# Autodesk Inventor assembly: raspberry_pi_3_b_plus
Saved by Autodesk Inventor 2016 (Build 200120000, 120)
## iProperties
Created: 2018-05
Part Number: raspberry_pi_3_b_plus
Document SubType Name: Assembly
Designer: Administrator
Title: raspberry_pi_3_b_plus v38
Author: Administrator
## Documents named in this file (33)
- c:\worker\convert-fusion-mar-2018\tmp\job-1\16\output\files\8c58ff39-88bb-4352-afd9-60265520bae5\05ab2b07-ca50-4e2e-bbe0-02242daedd4e.iam
- c:\worker\convert-fusion-mar-2018\tmp\job-1\16\output\files\8c58ff39-88bb-4352-afd9-60265520bae5\pcb.ipt
- c:\worker\convert-fusion-mar-2018\tmp\job-1\16\output\files\8c58ff39-88bb-4352-afd9-60265520bae5\micro_usb_connector v17.iam
- c:\worker\convert-fusion-mar-2018\tmp\job-1\16\output\files\8c58ff39-88bb-4352-afd9-60265520bae5\sd_card_slot_molex v11.iam
- c:\worker\convert-fusion-mar-2018\tmp\job-1\16\output\files\8c58ff39-88bb-4352-afd9-60265520bae5\Pin Header 20x2 TH Pitch 2.54mm v1.iam
- c:\worker\convert-fusion-mar-2018\tmp\job-1\16\output\files\8c58ff39-88bb-4352-afd9-60265520bae5\USB-A-stack-1x2 v23.iam
- c:\worker\convert-fusion-mar-2018\tmp\job-1\16\output\files\8c58ff39-88bb-4352-afd9-60265520bae5\USB-A-stack-1x2 v23_1.iam
- c:\worker\convert-fusion-mar-2018\tmp\job-1\16\output\files\8c58ff39-88bb-4352-afd9-60265520bae5\te_1-1734248-5.ipt
- c:\worker\convert-fusion-mar-2018\tmp\job-1\16\output\files\8c58ff39-88bb-4352-afd9-60265520bae5\Pin Header 2x2 TH Pitch 2.54mm v1.iam
- c:\worker\convert-fusion-mar-2018\tmp\job-1\16\output\files\8c58ff39-88bb-4352-afd9-60265520bae5\SOP-3_1.6mm.ipt
- c:\worker\convert-fusion-mar-2018\tmp\job-1\16\output\files\8c58ff39-88bb-4352-afd9-60265520bae5\EDAC_1743_RJ45_TH v18.iam
- c:\worker\convert-fusion-mar-2018\tmp\job-1\16\output\files\8c58ff39-88bb-4352-afd9-60265520bae5\qfn32_5mm v3.ipt
- c:\worker\convert-fusion-mar-2018\tmp\job-1\16\output\files\8c58ff39-88bb-4352-afd9-60265520bae5\qfn48_9mm v3.ipt
- c:\worker\convert-fusion-mar-2018\tmp\job-1\16\output\files\8c58ff39-88bb-4352-afd9-60265520bae5\TSOP-6 2mm v1.ipt
- c:\worker\convert-fusion-mar-2018\tmp\job-1\16\output\files\8c58ff39-88bb-4352-afd9-60265520bae5\TSOP-6 3mm v3.ipt
- c:\worker\convert-fusion-mar-2018\tmp\job-1\16\output\files\8c58ff39-88bb-4352-afd9-60265520bae5\qfp16_3x2mm v5.iam
- c:\worker\convert-fusion-mar-2018\tmp\job-1\16\output\files\8c58ff39-88bb-4352-afd9-60265520bae5\wifi.iam
- c:\worker\convert-fusion-mar-2018\tmp\job-1\16\output\files\8c58ff39-88bb-4352-afd9-60265520bae5\qfn80_12mm v3.ipt
- c:\worker\convert-fusion-mar-2018\tmp\job-1\16\output\files\8c58ff39-88bb-4352-afd9-60265520bae5\crystal_dfn4 v1.iam
- c:\worker\convert-fusion-mar-2018\tmp\job-1\16\output\files\8c58ff39-88bb-4352-afd9-60265520bae5\bcm2837 v8.ipt
- c:\worker\convert-fusion-mar-2018\tmp\job-1\16\output\files\8c58ff39-88bb-4352-afd9-60265520bae5\wlbga140_5mm v2.ipt
- c:\worker\convert-fusion-mar-2018\tmp\job-1\16\output\files\8c58ff39-88bb-4352-afd9-60265520bae5\cap0603_03 v2.ipt
- c:\worker\convert-fusion-mar-2018\tmp\job-1\16\output\files\8c58ff39-88bb-4352-afd9-60265520bae5\cap0402 v1.ipt
- c:\worker\convert-fusion-mar-2018\tmp\job-1\16\output\files\8c58ff39-88bb-4352-afd9-60265520bae5\resistor_0402 v1.ipt
- c:\worker\convert-fusion-mar-2018\tmp\job-1\16\output\files\8c58ff39-88bb-4352-afd9-60265520bae5\cap1206 v4.ipt
- c:\worker\convert-fusion-mar-2018\tmp\job-1\16\output\files\8c58ff39-88bb-4352-afd9-60265520bae5\ind2520 v1.ipt
- c:\worker\convert-fusion-mar-2018\tmp\job-1\16\output\files\8c58ff39-88bb-4352-afd9-60265520bae5\ledra_0603 v2.ipt
- c:\worker\convert-fusion-mar-2018\tmp\job-1\16\output\files\8c58ff39-88bb-4352-afd9-60265520bae5\pj-322 v8.iam
- c:\worker\convert-fusion-mar-2018\tmp\job-1\16\output\files\8c58ff39-88bb-4352-afd9-60265520bae5\SOP-3 v1.ipt
- c:\worker\convert-fusion-mar-2018\tmp\job-1\16\output\files\8c58ff39-88bb-4352-afd9-60265520bae5\SOP-3 2.5mm v3.ipt
- c:\worker\convert-fusion-mar-2018\tmp\job-1\16\output\files\8c58ff39-88bb-4352-afd9-60265520bae5\capar2_1013 v1.ipt
- c:\worker\convert-fusion-mar-2018\tmp\job-1\16\output\files\8c58ff39-88bb-4352-afd9-60265520bae5\molex hdmi smt v8.iam
- c:\worker\convert-fusion-mar-2018\tmp\job-1\16\output\files\8c58ff39-88bb-4352-afd9-60265520bae5\TSOP-2 4mm v2.ipt
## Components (213 placed, 32 different names)
1. pcb:1
2. micro_usb_connector v17:1 [sub-assembly]
3. sd_card_slot_molex v11:1 [sub-assembly]
4. Pin Header 20x2 TH Pitch 2.54mm v1:1 [sub-assembly]
5. USB-A-stack-1x2 v23:1 [sub-assembly]
6. USB-A-stack-1x2 v23:2 [sub-assembly]
7. te_1-1734248-5:1
8. Pin Header 2x2 TH Pitch 2.54mm v1:1 [sub-assembly]
9. te_1-1734248-5:2
10. SOP-3_1.6mm:1
11. EDAC_1743_RJ45_TH v18:1 [sub-assembly]
12. SOP-3_1.6mm:1:1
13. SOP-3_1.6mm:2
14. SOP-3_1.6mm:3
15. qfn32_5mm v3:1
16. qfn48_9mm v3:1
17. TSOP-6 2mm v1:1
18. TSOP-6 3mm v3:1
19. qfp16_3x2mm v5:1 [sub-assembly]
20. wifi:1 [sub-assembly]
21. qfn80_12mm v3:1
22. crystal_dfn4 v1:1 [sub-assembly]
23. bcm2837 v8:1
24. wlbga140_5mm v2:1
25. cap0603_03 v2:1
26. cap0603_03 v2:2
27. cap0603_03 v2:3
28. cap0603_03 v2:4
29. cap0603_03 v2:5
30. cap0603_03 v2:6
31. cap0603_03 v2:7
32. cap0603_03 v2:8
33. cap0402 v1:1
34. cap0402 v1:2
35. cap0402 v1:3
36. cap0402 v1:4
37. cap0402 v1:5
38. cap0402 v1:6
39. cap0402 v1:7
40. cap0402 v1:8
41. cap0402 v1:9
42. cap0402 v1:10
43. cap0402 v1:11
44. cap0402 v1:12
45. cap0402 v1:13
46. cap0402 v1:14
47. cap0402 v1:15
48. cap0402 v1:16
49. cap0402 v1:17
50. cap0402 v1:18
51. cap0402 v1:19
52. cap0402 v1:20
53. cap0402 v1:21
54. cap0402 v1:22
55. cap0402 v1:23
56. cap0402 v1:24
57. cap0402 v1:25
58. cap0402 v1:26
59. cap0402 v1:27
60. cap0402 v1:28
61. cap0402 v1:29
62. cap0402 v1:30
63. cap0402 v1:31
64. cap0402 v1:32
65. cap0402 v1:33
66. cap0402 v1:34
67. cap0402 v1:35
68. cap0402 v1:36
69. cap0402 v1:37
70. resistor_0402 v1:1
71. resistor_0402 v1:2
72. resistor_0402 v1:3
73. resistor_0402 v1:4
74. resistor_0402 v1:5
75. cap0402 v1:38
76. cap0402 v1:39
77. resistor_0402 v1:6
78. cap0402 v1:40
79. cap0402 v1:41
80. resistor_0402 v1:7
81. resistor_0402 v1:8
82. resistor_0402 v1:9
83. resistor_0402 v1:10
84. resistor_0402 v1:11
85. resistor_0402 v1:12
86. resistor_0402 v1:13
87. resistor_0402 v1:14
88. resistor_0402 v1:15
89. resistor_0402 v1:16
90. resistor_0402 v1:17
91. resistor_0402 v1:18
92. resistor_0402 v1:19
93. resistor_0402 v1:20
94. resistor_0402 v1:21
95. resistor_0402 v1:22
96. resistor_0402 v1:23
97. resistor_0402 v1:24
98. resistor_0402 v1:25
99. resistor_0402 v1:26
100. resistor_0402 v1:27
101. resistor_0402 v1:28
102. resistor_0402 v1:29
103. resistor_0402 v1:30
104. resistor_0402 v1:31
105. resistor_0402 v1:32
106. resistor_0402 v1:33
107. resistor_0402 v1:34
108. resistor_0402 v1:35
109. resistor_0402 v1:36
110. resistor_0402 v1:37
111. resistor_0402 v1:38
112. cap0402 v1:42
113. resistor_0402 v1:39
114. resistor_0402 v1:40
115. cap1206 v4:1
116. cap1206 v4:2
117. cap1206 v4:3
118. cap1206 v4:4
119. cap1206 v4:5
120. cap1206 v4:6
121. cap1206 v4:7
122. cap1206 v4:8
123. cap1206 v4:9
124. cap1206 v4:10
125. cap1206 v4:11
126. cap0603_03 v2:9
127. cap0603_03 v2:10
128. cap0603_03 v2:11
129. cap0603_03 v2:12
130. cap0603_03 v2:13
131. cap0603_03 v2:14
132. cap0603_03 v2:15
133. crystal_dfn4 v1:2 [sub-assembly]
134. resistor_0402 v1:41
135. resistor_0402 v1:42
136. resistor_0402 v1:43
137. resistor_0402 v1:44
138. resistor_0402 v1:45
139. resistor_0402 v1:46
140. resistor_0402 v1:47
141. resistor_0402 v1:48
142. resistor_0402 v1:49
143. resistor_0402 v1:50
144. resistor_0402 v1:51
145. resistor_0402 v1:52
146. resistor_0402 v1:53
147. resistor_0402 v1:54
148. resistor_0402 v1:55
149. resistor_0402 v1:56
150. resistor_0402 v1:57
151. cap0402 v1:43
152. cap0402 v1:44
153. cap0402 v1:45
154. cap0402 v1:46
155. ind2520 v1:1
156. ind2520 v1:2
157. ind2520 v1:3
158. ind2520 v1:4
159. ledra_0603 v2:1
160. ledra_0603 v2:2
161. pj-322 v8:1 [sub-assembly]
162. SOP-3 v1:1
163. SOP-3 2.5mm v3:1
164. capar2_1013 v1:1
165. capar2_1013 v1:2
166. capar2_1013 v1:3
167. capar2_1013 v1:4
168. molex hdmi smt v8:1 [sub-assembly]
169. TSOP-2 4mm v2:1
170. cap0402 v1:47
171. cap0402 v1:48
172. cap0402 v1:49
173. cap0402 v1:50
174. cap0402 v1:51
175. cap0402 v1:52
176. cap0402 v1:53
177. cap0402 v1:54
178. cap0402 v1:55
179. cap0402 v1:56
180. cap0402 v1:57
181. cap0402 v1:58
182. cap0402 v1:59
183. cap0402 v1:60
184. cap0402 v1:61
185. cap0402 v1:62
186. cap0402 v1:63
187. cap0402 v1:64
188. cap0402 v1:65
189. cap0402 v1:66
190. cap0402 v1:67
191. cap0402 v1:68
192. cap0402 v1:69
193. cap0402 v1:70
194. cap0402 v1:71
195. cap0402 v1:72
196. cap0402 v1:73
197. cap0402 v1:74
198. cap0402 v1:75
199. cap0402 v1:76
200. cap0402 v1:77
201. cap0402 v1:78
202. cap0402 v1:79
203. cap0402 v1:80
204. cap0402 v1:81
205. cap0402 v1:82
206. cap0402 v1:83
207. cap0402 v1:84
208. cap0402 v1:85
209. cap0402 v1:86
210. cap0402 v1:87
211. cap0402 v1:88
212. cap0402 v1:89
213. cap0402 v1:90
